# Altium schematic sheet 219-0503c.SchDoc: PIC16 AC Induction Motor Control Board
size C; DrawnBy: Justin Bauer; DocumentNumber: 219-0503; Revision: C; PageSetup: Record=PageOptions¦CenterHorizontal=True¦CenterVertical=True¦PrintScale=0.72¦XCorrection=1.00¦YCorrection=1.00¦PrintKind=2¦BorderSize=5000000¦LeftOffset=0¦BottomOffset=0¦Orientation=2¦PaperLength=1000¦PaperWidth=1000¦Scale=100¦PaperSource=257¦PrintQuality=600¦MediaType=1¦DitherType=10¦PaperKind=11 x 17¦PrintScaleMode=1
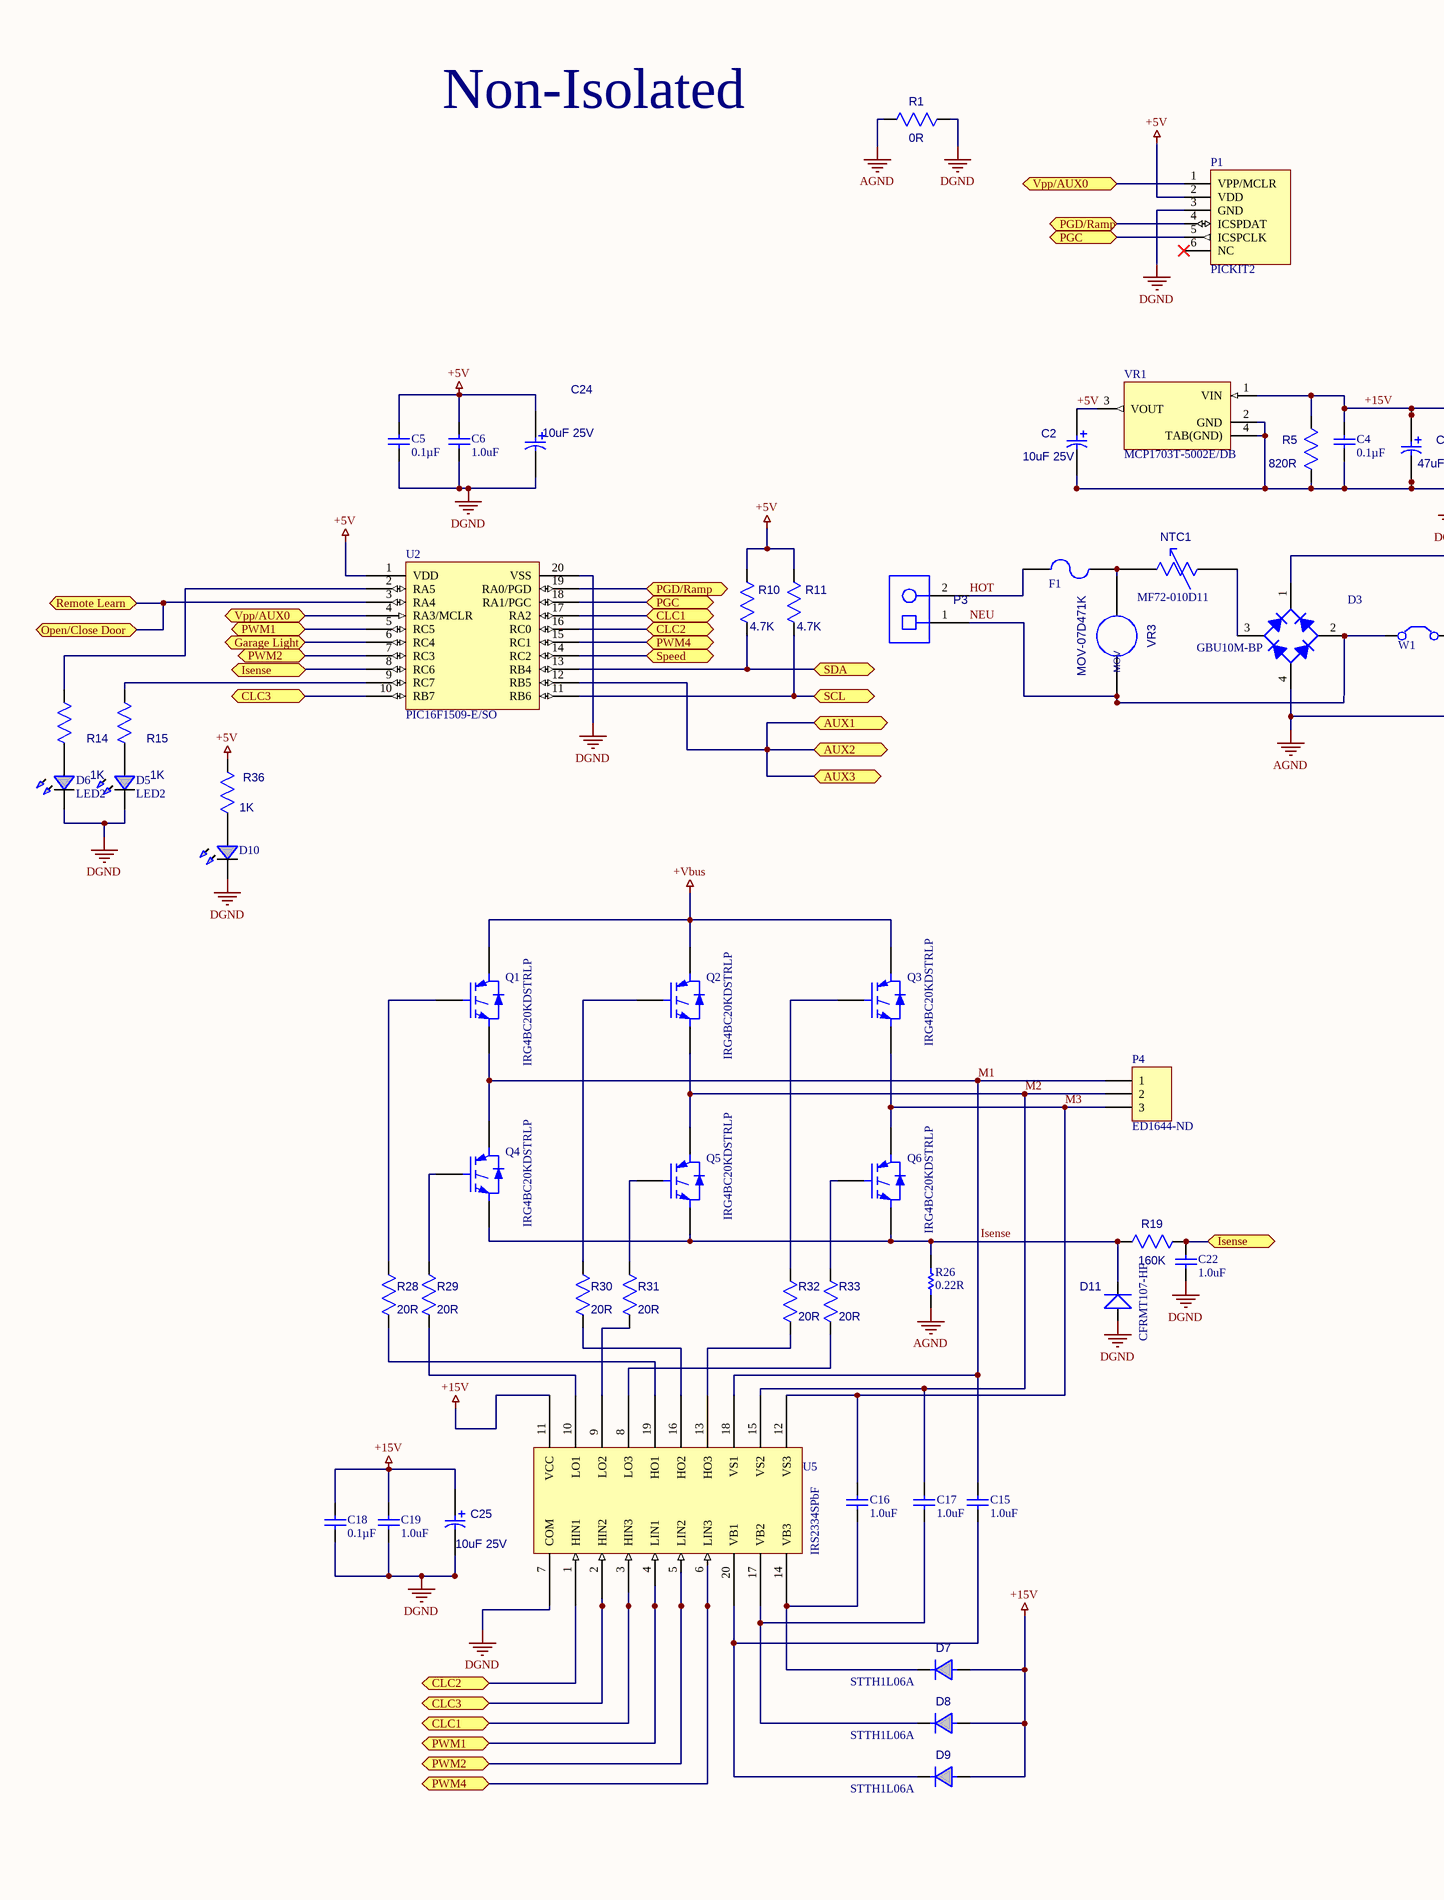
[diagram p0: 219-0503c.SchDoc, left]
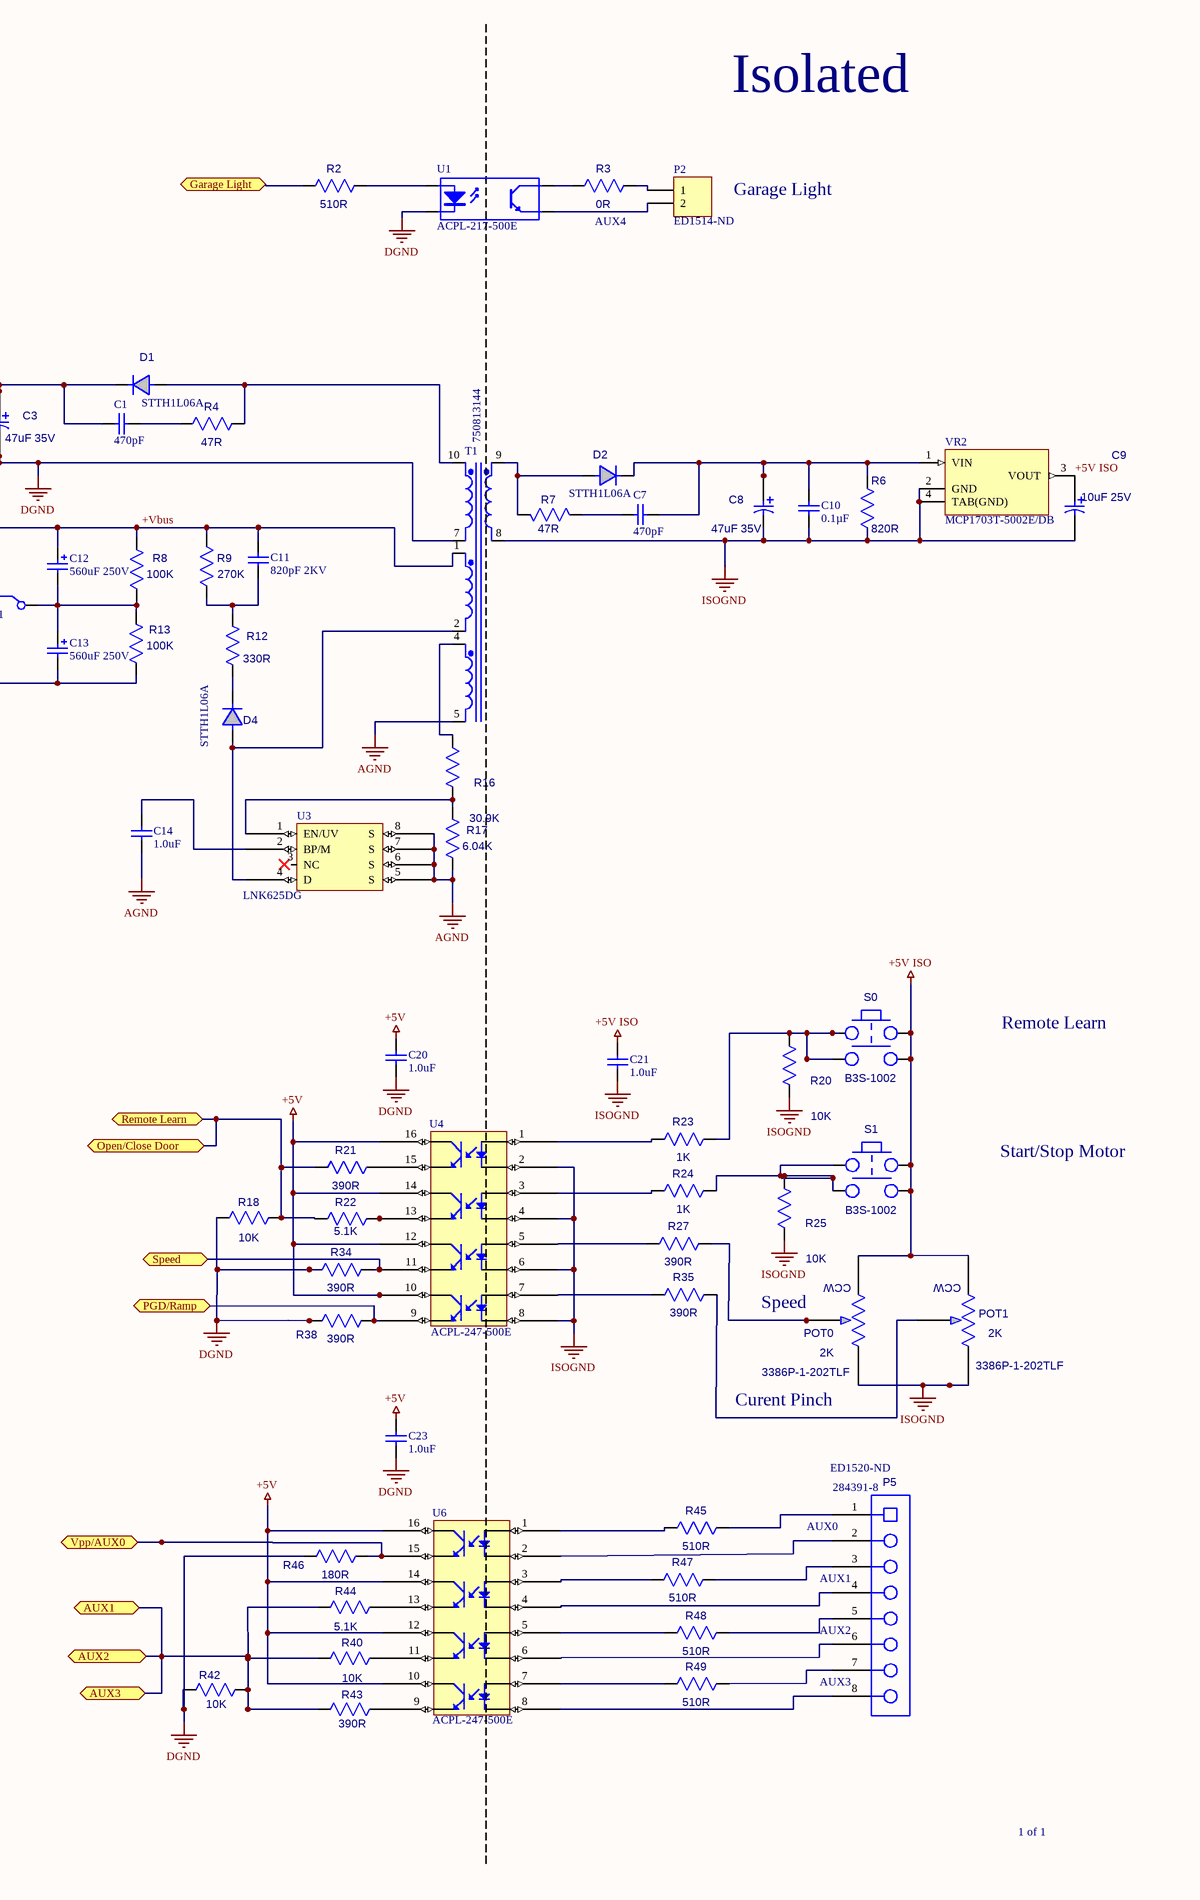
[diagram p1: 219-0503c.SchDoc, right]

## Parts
C1  value 470pF  [CAP_0805]  (hidden comment: CAP0805_470pF)
C2  value 10uF 25V  [CAP079in_5mm]  (hidden comment: UVZ1E100MDD)
C3  value 47uF 35V  [CAP079in_5mm]  (hidden comment: ESH476M035AE3AA)
C4  value 0.1µF  [CAP_0805]  (hidden comment: CAP0805_0.1uF_50V)
C5  value 0.1µF  [CAP_0805]  (hidden comment: CAP0805_0.1uF_50V)
C6  value 1.0uF  [CAP_0805]  (hidden comment: CAP0805_1uF)
C7  value 470pF  [CAP_0805]  (hidden comment: CAP0805_470pF)
C8  value 47uF 35V  [CAP079in_5mm]  (hidden comment: ESH476M035AE3AA)
C9  value 10uF 25V  [CAP079in_5mm]  (hidden comment: UVZ1E100MDD)
C10  value 0.1µF  [CAP_0805]  (hidden comment: CAP0805_0.1uF_50V)
C11  value 820pF 2KV  [CAP_1210]  (hidden comment: CAP1210_820pF)
C12  value 560uF 250V  [CAPPRS10-25x50]  (hidden comment: CAP_560uF_250V)
C13  value 560uF 250V  [CAPPRS10-25x50]  (hidden comment: CAP_560uF_250V)
C14  value 1.0uF  [CAP_0805]  (hidden comment: CAP0805_1uF)
C15  value 1.0uF  [CAP_0805]  (hidden comment: CAP0805_1uF)
C16  value 1.0uF  [CAP_0805]  (hidden comment: CAP0805_1uF)
C17  value 1.0uF  [CAP_0805]  (hidden comment: CAP0805_1uF)
C18  value 0.1µF  [CAP_0805]  (hidden comment: CAP0805_0.1uF_50V)
C19  value 1.0uF  [CAP_0805]  (hidden comment: CAP0805_1uF)
C20  value 1.0uF  [CAP_0805]  (hidden comment: CAP0805_1uF)
C21  value 1.0uF  [CAP_0805]  (hidden comment: CAP0805_1uF)
C22  value 1.0uF  [CAP_0805]  (hidden comment: CAP0805_1uF)
C23  value 1.0uF  [CAP_0805]  (hidden comment: CAP0805_1uF)
C24  value 10uF 25V  [CAP079in_5mm]  (hidden comment: UVZ1E100MDD)
C25  value 10uF 25V  [CAP079in_5mm]  (hidden comment: UVZ1E100MDD)
D1  Part Number: STTH1L06A  [DIODE-SMA]  (hidden comment: DIODE-SMA_STTH1L06A)
D2  Part Number: STTH1L06A  [DIODE-SMA]  (hidden comment: DIODE-SMA_STTH1L06A)
D3  Part Number: GBU10M-BP  [DiodeBridge]  (hidden comment: Bridge1)
D4  Part Number: STTH1L06A  [DIODE-SMA]  (hidden comment: DIODE-SMA_STTH1L06A)
D5  LED2  [LED_0805_RED]
D6  LED2  [LED_0805_GRN]
D7  Part Number: STTH1L06A  [DIODE-SMA]  (hidden comment: DIODE-SMA_STTH1L06A)
D8  Part Number: STTH1L06A  [DIODE-SMA]  (hidden comment: DIODE-SMA_STTH1L06A)
D9  Part Number: STTH1L06A  [DIODE-SMA]  (hidden comment: DIODE-SMA_STTH1L06A)
D10  LED2  [LED_0805_GRN]  (value not drawn)
D11  CFRMT107-HF  [TC3216]
F1  Fuse 2  [FuseSocketHolder]  (value not drawn)
NTC1  MF72-010D11  [THERM_NTC_7.5MM_THERM_NTC_7.5MM(Primary)]
P1  PICKIT2  [TERMSTRIP_TSW-106-07-F-S]
P2  Supplier Part Number 1: ED1514-ND  [TERM BLOCK, 2POS, 3.81.mm]  (hidden comment: ED555/2DS)
P3  OSTTC022162  [2PHDR-200]  (value not drawn)
P4  Supplier Part Number 1: ED1644-ND  [3PHDRX200]  (hidden comment: EDZ350/3)
P5  Part Number1: 284391-8  Supplier Part Number 2: ED1520-ND  [TERM BLOCK, 8POS, 3.5mm]  (hidden comment: Term_BLK_8pos 3.5mm)
POT0  3386P-1-202TLF  value 2K  [POT3386P-1-XXXT]
POT1  3386P-1-202TLF  value 2K  [POT3386P-1-XXXT]
Q1  Part Number: IRG4BC20KDSTRLP  [D2PAK]  (hidden comment: IRG4BC20KD-S_1)
Q2  Part Number: IRG4BC20KDSTRLP  [D2PAK]  (hidden comment: IRG4BC20KD-S_1)
Q3  Part Number: IRG4BC20KDSTRLP  [D2PAK]  (hidden comment: IRG4BC20KD-S_1)
Q4  Part Number: IRG4BC20KDSTRLP  [D2PAK]  (hidden comment: IRG4BC20KD-S_1)
Q5  Part Number: IRG4BC20KDSTRLP  [D2PAK]  (hidden comment: IRG4BC20KD-S_1)
Q6  Part Number: IRG4BC20KDSTRLP  [D2PAK]  (hidden comment: IRG4BC20KD-S_1)
R1  value 0R  [RC_0805]  (hidden comment: RES_RC0805)
R2  value 510R  [RC_0805]  (hidden comment: RES_RC0805)
R3  value 0R  [RC_0805]  (hidden comment: RES_RC0805)
R4  value 47R  [RC_0805]  (hidden comment: RES_RC0805)
R5  value 820R  [RC_0805]  (hidden comment: RES_RC0805)
R6  value 820R  [RC_0805]  (hidden comment: RES_RC0805)
R7  value 47R  [RC_0805]  (hidden comment: RES_RC0805)
R8  value 100K  [RES400_RES400(Primary)]  (hidden comment: CF14JT100K)
R9  value 270K  [RES300_RES300(Primary)]  (hidden comment: RNMF14FTC270K)
R10  value 4.7K  [RC_0805]  (hidden comment: RES_RC0805)
R11  value 4.7K  [RC_0805]  (hidden comment: RES_RC0805)
R12  value 330R  [RES400_RES400(Primary)]  (hidden comment: CF14JT330R)
R13  value 100K  [RES400_RES400(Primary)]  (hidden comment: CF14JT100K)
R14  value 1K  [RC_0805]  (hidden comment: RES_RC0805)
R15  value 1K  [RC_0805]  (hidden comment: RES_RC0805)
R16  value 30.9K  [RC_0805]  (hidden comment: RMCF0805FT30K9)
R17  value 6.04K  [RC_0805]  (hidden comment: RNCP0805FTD6K04)
R18  value 10K  [RC_0805]  (hidden comment: RES_RC0805)
R19  value 160K  [RC_0805]  (hidden comment: RES_RC0805)
R20  value 10K  [RC_0805]  (hidden comment: RES_RC0805)
R21  value 390R  [RC_0805]  (hidden comment: RES_RC0805)
R22  value 5.1K  [RC_0805]  (hidden comment: RES_RC0805)
R23  value 1K  [RC_0805]  (hidden comment: RES_RC0805)
R24  value 1K  [RC_0805]  (hidden comment: RES_RC0805)
R25  value 10K  [RC_0805]  (hidden comment: RES_RC0805)
R26  value 0.22R  [PowerResistor - 5W SQM 5MM Radial]  (hidden comment: 2-1623788-5)
R27  value 390R  [RC_0805]  (hidden comment: RES_RC0805)
R28  value 20R  [RC_0805]  (hidden comment: RES_RC0805)
R29  value 20R  [RC_0805]  (hidden comment: RES_RC0805)
R30  value 20R  [RC_0805]  (hidden comment: RES_RC0805)
R31  value 20R  [RC_0805]  (hidden comment: RES_RC0805)
R32  value 20R  [RC_0805]  (hidden comment: RES_RC0805)
R33  value 20R  [RC_0805]  (hidden comment: RES_RC0805)
R34  value 390R  [RC_0805]  (hidden comment: RES_RC0805)
R35  value 390R  [RC_0805]  (hidden comment: RES_RC0805)
R36  value 1K  [RC_0805]  (hidden comment: RES_RC0805)
R38  value 390R  [RC_0805]  (hidden comment: RES_RC0805)
R40  value 10K  [RC_0805]  (hidden comment: RES_RC0805)
R42  value 10K  [RC_0805]  (hidden comment: RES_RC0805)
R43  value 390R  [RC_0805]  (hidden comment: RES_RC0805)
R44  value 5.1K  [RC_0805]  (hidden comment: RES_RC0805)
R45  value 510R  [RC_0805]  (hidden comment: RES_RC0805)
R46  value 180R  [RC_0805]  (hidden comment: RMCF0805FT180R)
R47  value 510R  [RC_0805]  (hidden comment: RES_RC0805)
R48  value 510R  [RC_0805]  (hidden comment: RES_RC0805)
R49  value 510R  [RC_0805]  (hidden comment: RES_RC0805)
S0  B3S-1002  [SW-B3S1002]
S1  B3S-1002  [SW-B3S1002]
T1  750813144  [Trans_750813134]
U1  ACPL-217-500E  [so4_wstep]
U2  Part Number: PIC16F1509-E/SO  [SO20]  (hidden comment: PIC16F1509-I/SO)
U3  LNK625DG  [so8]
U4  ACPL-247-500E  [SOP127P762-16L]
U5  IRS2334SPbF  [so20]
U6  ACPL-247-500E  [SOP127P762-16L]
VR1  MCP1703T-5002E/DB  [SOT223-3]
VR2  MCP1703T-5002E/DB  [SOT223-3]
VR3  value MOV-07D471K  [MOV_ERZ-V07D431_MOV_ERZ-V07D431(Primary)]  (hidden comment: MOV_MOV-07D471K)
W1  286 SV001  [HEADER_156sp_1X2_DNP]  (value not drawn)  (no BOM)

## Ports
AUX1, AUX2, AUX3, CLC1, CLC2, CLC3, Garage Light, Isense, Open/Close Door, PGC, PGD/Ramp, PWM1, PWM2, PWM4, Remote Learn, SCL, SDA, Speed, Vpp/AUX0

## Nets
+5V: C2.1 C5.2(B) C6.2(B) C20.1(A) C23.1(A) C24.1 P1.2(VDD) R10.2(RO) R11.2(RO) R36.2(RO) U2.1(VDD) U4.10 U4.12 U4.14 U4.16 U6.10 U6.12 U6.14 U6.16 VR1.3(VOUT)
+5V ISO: C9.1 C21.1(A) POT0.1(CCW) POT1.1(CCW) S0.3 S0.4 S1.3 S1.4 VR2.3(VOUT)
+15V: C1.1(A) C3.1 C4.2(B) C18.2(B) C19.2(B) C25.1 D1.1(K) D7.2(A) D8.2(A) D9.2(A) R5.2(RO) U5.11(VCC) VR1.1(VIN)
+Vbus: C11.2(B) C12.1 D3.1(K) Q1.2(C) Q2.2(C) Q3.2(C) R8.B R9.B T1.1(Pri-)
AGND: C13.2 C14.1(A) D3.4(A) R1.1(RI) R13.A R17.1(RI) R26.1 T1.5(Sec3-) U3.5(S) U3.6(S) U3.7(S) U3.8(S)
DGND: C2.2 C3.2 C4.1(A) C5.1(A) C6.1(A) C18.1(A) C19.1(A) C20.2(B) C22.1(A) C23.2(B) C24.2 C25.2 D5.1(K) D6.1(K) D10.1(K) D11.1(A) P1.3(GND) R1.2(RO) R5.1(RI) R18.2(RO) R34.1(RI) R38.1(RI) R42.2(RO) R46.1(RI) T1.7(Sec1-) U1.2(K) U2.20(VSS) U5.7(COM) VR1.2(GND) VR1.4(TAB(GND))
ISOGND: C8.2 C9.2 C10.2(B) C21.2(B) POT0.3(CW) POT1.3(CW) R6.1(RI) R20.1(RI) R25.1(RI) T1.8(Sec-) U4.2 U4.4 U4.6 U4.8 VR2.2(GND) VR2.4(TAB(GND))
AUX1: R40.2(RO) R42.1(RI) R43.2(RO) R44.2(RO) U2.12(RB5) ; port AUX1, port AUX2, port AUX3
CLC1: U2.17(RA2) U5.3(HIN3) ; port CLC1
CLC2: U2.16(RC0) U5.1(HIN1) ; port CLC2
CLC3: U2.10(RB7) U5.2(HIN2) ; port CLC3
Garage Light: R2.1(RI) U2.6(RC4) ; port Garage Light
HOT: F1.1 P3.2(P2)
Isense: D11.2(K) Q4.3(E) Q5.3(E) Q6.3(E) R19.1(RI) R26.2
Isense: C22.2(B) R19.2(RO) U2.8(RC6) ; port Isense  [a separate net that carries the same name]
M1: C15.2(B) P4.1 Q1.3(E) Q4.2(C) U5.18(VS1)
M2: C17.1(A) P4.2 Q2.3(E) Q5.2(C) U5.15(VS2)
M3: C16.2(B) P4.3 Q3.3(E) Q6.2(C) U5.12(VS3)
NEU: D3.2(C) P3.1(P1) VR3.B W1.1(C1)
Open/Close Door: R18.1(RI) R21.2(RO) R22.2(RO) U2.3(RA4) ; port Remote Learn, port Open/Close Door
PGC: P1.5(ICSPCLK) U2.18(RA1/PGC) ; port PGC
PGD/Ramp: P1.4(ICSPDAT) R38.2(RO) U2.19(RA0/PGD) U4.9 ; port PGD/Ramp
PWM1: U2.5(RC5) U5.4(LIN1) ; port PWM1
PWM2: U2.7(RC3) U5.5(LIN2) ; port PWM2
PWM4: U2.15(RC1) U5.6(LIN3) ; port PWM4
SCL: R11.1(RI) U2.11(RB6) ; port SCL
SDA: R10.1(RI) U2.13(RB4) ; port SDA
Speed: R34.2(RO) U2.14(RC2) U4.11 ; port Speed
Vpp/AUX0: P1.1(VPP/MCLR) R46.2(RO) U2.4(RA3/MCLR) U6.15 ; port Vpp/AUX0
NetC1_2: C1.2(B) R4.1(RI)
NetC7_1: C7.1(A) R7.1(RI)
NetC7_2: C7.2(B) C8.1 C10.1(A) D2.1(K) R6.2(RO) VR2.1(VIN)
NetC11_1: C11.1(A) R9.A R12.B
NetC12_2: C12.2 C13.1 R8.A R13.B W1.2(C2)
NetC14_2: C14.2(B) U3.2(BP/M)
NetC15_1: C15.1(A) D9.1(K) U5.20(VB1)
NetC16_1: C16.1(A) D7.1(K) U5.14(VB3)
NetC17_2: C17.2(B) D8.1(K) U5.17(VB2)
NetD1_2: D1.2(A) R4.2(RO) T1.10(Sec1+)
NetD2_2: D2.2(A) R7.2(RO) T1.9(Sec+)
NetD3_3: D3.3(C) NTC1.1
NetD4_1: D4.1(K) R12.A
NetD4_2: D4.2(A) T1.2(PRI+) U3.4(D)
NetD5_2: D5.2(A) R15.1(RI)
NetD6_2: D6.2(A) R14.1(RI)
NetD10_2: D10.2(A) R36.1(RI)
NetF1_2: F1.2 NTC1.2 VR3.A
NetP2_1: P2.1 R3.2(RO)
NetP2_2: P2.2 U1.3(E)
NetP5_1: P5.1(P1) R45.2(RO)
NetP5_2: P5.2(P2) U6.2
NetP5_3: P5.3(P3) R47.2(RO)
NetP5_4: P5.4(P4) U6.4
NetP5_5: P5.5(P5) R48.2(RO)
NetP5_6: P5.6(P6) U6.6
NetP5_7: P5.7(P7) R49.2(RO)
NetP5_8: P5.8(P8) U6.8
NetPOT0_2: POT0.2(WIPER) R27.2(RO)
NetPOT1_2: POT1.2(WIPER) R35.2(RO)
NetQ1_1: Q1.1(G) R28.2(RO)
NetQ2_1: Q2.1(G) R30.2(RO)
NetQ3_1: Q3.1(G) R32.2(RO)
NetQ4_1: Q4.1(G) R29.2(RO)
NetQ5_1: Q5.1(G) R31.2(RO)
NetQ6_1: Q6.1(G) R33.2(RO)
NetR2_2: R2.2(RO) U1.1(A)
NetR3_1: R3.1(RI) U1.4(C)
NetR14_2: R14.2(RO) U2.2(RA5)
NetR15_2: R15.2(RO) U2.9(RC7)
NetR16_1: R16.1(RI) R17.2(RO) U3.1(EN/UV)
NetR16_2: R16.2(RO) T1.4(Sec3+)
NetR20_2: R20.2(RO) R23.2(RO) S0.1 S0.2
NetR21_1: R21.1(RI) U4.15
NetR22_1: R22.1(RI) U4.13
NetR23_1: R23.1(RI) U4.1
NetR24_1: R24.1(RI) U4.3
NetR24_2: R24.2(RO) R25.2(RO) S1.1 S1.2
NetR27_1: R27.1(RI) U4.5
NetR28_1: R28.1(RI) U5.19(HO1)
NetR29_1: R29.1(RI) U5.10(LO1)
NetR30_1: R30.1(RI) U5.16(HO2)
NetR31_1: R31.1(RI) U5.9(LO2)
NetR32_1: R32.1(RI) U5.13(HO3)
NetR33_1: R33.1(RI) U5.8(LO3)
NetR35_1: R35.1(RI) U4.7
NetR40_1: R40.1(RI) U6.11
NetR43_1: R43.1(RI) U6.9
NetR44_1: R44.1(RI) U6.13
NetR45_1: R45.1(RI) U6.1
NetR47_1: R47.1(RI) U6.3
NetR48_1: R48.1(RI) U6.5
NetR49_1: R49.1(RI) U6.7

Not connected (* = marked no-connect by the designer): P1 6(NC)*; U3 3(NC)

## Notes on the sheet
- Isolated
- Non-Isolated
- (near R3) AUX4
- Garage Light
- Remote Learn
- Start/Stop Motor
- Speed
- (near POT0) Curent Pinch
- (near P5) AUX0
- (near P5) AUX1
- (near P5) AUX2
- (near P5) AUX3
- 1 of 1

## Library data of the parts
C1 C7 = CAP0805_470pF: CAP CER 470PF 100V 5% NP0 0805; Part Number: CL21C471JCCNNNC; Dielectric Characteristic: C0G; Voltage Rating: 100; Capacitor Case Style: 0805; No. of Pins: 2
C2 C9 C24 C25 = CAP100RP_10uF_25V: CAP ALUM 10UF 25V 20% RADIAL
C3 C8 = CAP100RP_47uF_35V: CAP ALUM 47UF 35V 20% RADIAL
C4 C5 C10 = CAP0805_0.1uF_50V: Cap, Ceramic, 0.1uF, 50V X7R; Part Number: 08055C104MAT2A; Manufacturer 1: AVX Corporation; Tolerance: ±20%
C6 C14-C17 C19-C23 = CAP0805_1uF: CAP CER 1UF 50V 10% X5R 080; Part Number: UMK212BJ105KG-T; Dielectric Characteristic: X7; Voltage Rating: 50; Capacitor Case Style: 0805; No. of Pins: 2
C11 = CAP1210_820pF: CAP CER 820PF 2KV 10% X7R 1210; Manufacturer: TDK; Part Number: 1210GC821KAT1A; Dielectric Characteristic: X5; Capacitance Tolerance: ± 20%; Voltage Rating: 2000; Temperature Coefficient: ± 15%; Capacitor Case Style: 0805; No. of Pins: 2; Tolerance: ±20%
C12 C13 = CAP_560uF_250V: CAP ALUM 560UF 250V 20% SNAP; Part Number: EET-UQ2E561CA
C18 = CAP0805_0.1uF_50V: Cap, Ceramic, 0.1uF, 50V X7R; Manufacturer 1: AVX Corporation; Manufacturer Part Number 1: 08055C104MAT2A; Tolerance: ±20%
D1 D2 D4 D7-D9 = DIODE-SMA_STTH1L06A: DIODE ULTRA FAST 600V 1A SMA; Manufacturer: ST Microelectronics; Value: {Value}
D3 = Bridge1: Full Wave Diode Bridge
D5 = LED_0805_YEL: LED, SMD, YEL, 0805 package; Manufacturer: Kingbright Corp; Part Number: APT2012YC; Color: Yellow; Current - Test: 20mA; Wavelength - Dominant: 588nm; Wavelength - Peak: 590nm; Millicandela Rating: 150mcd; Voltage - Forward (Vf) Typ: 2V; Lens Type: Clear; Lens Style/Size: Rectangle, 1.3mm x 1.25mm; Viewing Angle: 120°
D6 D10 = LED_0805_GRN: LED, SMD, GRN, 0805 package; Manufacturer: Kingbright Corp; Part Number: APT2012CGCK; Color: Green; Current - Test: 20mA; Wavelength - Dominant: 570nm; Wavelength - Peak: 574nm; Millicandela Rating: 50mcd; Voltage - Forward (Vf) Typ: 2.1V; Lens Type: Clear; Lens Style/Size: Rectangle, 1.3mm x 1.25mm; Viewing Angle: 120°
D11 = DIODE_FAST_SOD123
F1 = Fuse 2: FUSEHOLDER 22.5MM PCB 5X20MM BK; Part Number: 0031.8201
NTC1 = THERM_NTC_MF72-010D11: Current Limiter Inrush 100R 20%
P1 = HEADER_1X6_PICKIT2: Header, Pickit2, 1X6 0.1sp; Manufacturer: SAMTEC; Part Number: TSW-106-07-F-S
P2 = HDR_TERM_BLK3.5mm2POS: TERMINAL BLOCK 3.5MM 2POS PCB
P3 = 2PHDR-200: Value: {Value}
P4 = HDR_TERM_BLK5.08mm3POS: TERMINAL BLOCK 5.08MM 3POS PCB
P5 = Term_BLK_8pos 3.5mm: Part Number: ED555/8DS
POT0 POT1 = POT-3386P-1-202TLF
Q1-Q6 = IRG4BC20KD-S_1: Insulated Gate Bipolar Transistor with Ultrafast Soft Recovery Diode; Note: Terminal 2 (collector) is the BASE
R1 = RES_RC0805_0R: RES 0.0 OHM 1/8W 0805 SMD; Part Number: RMCF0805ZT0R00; Manufacturer: Stackpole Electronics; Suplier1: Digikey
R2 = RES_RC0805_510R: RES 510 OHM 1/8W 0805 SMD; Part Number: RMCF0805FT510R; Manufacturer: Stackpole Electronics
R3 = RES_RC0805_0R: RES 0.0 OHM 1/8W 0805 SMD; Manufacturer: Stackpole Electronics; Part Number: RMCF0805ZT0R00; Suplier1: Digikey
R4 R7 = RES_RC0805_47R: RES 47 OHM 1/8W 0805 SMD; Manufacturer Part Number: RMCF0805FT47R0; Manufacturer: Stackpole Electronics; Suplier1: Digikey
R5 R6 = RES_RC0805_820R: RES 820 OHM 1/8W 0805 SMD; Manufacturer Part Number: RMCF0805FT820R; Manufacturer: Stackpole Electronics
R8 R13 = RES400_100K: RES 100K OHM 1/4W 5% CARBON FILM
R9 = RES300_270K: RES 270K OHM 1/4W 5% CARBON FILM
R10 R11 = RES_RC0805_4.7K: RES 4.7K OHM 1/8W 1% 0805 SMD; Manufacturer: Stackpole Electronics; Manufacturer Part Number: RMCF0805FT4K70
R12 = RES400_330R: RES 330 OHM 1/4W 5% CARBON FILM
R14 R15 R23 R24 R36 = RES_RC0805_1K: RES 1K OHM 1/8W 1% 0805 SMD; Manufacturer Part Number: RMCF0805FT1K00; Manufacturer: Stackpole Electronics; Suplier1: Digikey
R16 = RES_RC0805_30.9K: RES 30.9K OHM 1/8W 1% 0805 SMD; Manufacturer: Stackpole Electronics
R17 = RES_RC0805_6.04K: RES 6.04K OHM 1/8W 1% 0805 SMD; Manufacturer: Stackpole Electronics
R18 R20 R25 R40 R42 = RES_RC0805_10K: RES 10K OHM 1/8W 1% 0805 SMD; Manufacturer Part Number: RMCF0805FT10K0; Manufacturer: Stackpole Electronics
R19 = RES_RC0805_160K: RES 160K OHM 1/8W 1% 0805 SMD; Manufacturer Part Number: RMCF0805FT160K; Manufacturer: Stackpole Electronics; Suplier1: Digikey
R21 R27 R34 R35 R38 R43 = RES_RC0805_390R: RES 390 OHM 1/8W 0805 SMD; Manufacturer Part Number: RMCF0805FT390R; Manufacturer: Stackpole Electronics
R22 R44 = RES_RC0805_5.1K: RES 5.1K OHM 1/8W 1% 0805 SMD; Manufacturer Part Number: RMCF0805FT5K10; Manufacturer: Stackpole Electronics
R26 = Res_5W_0R22vertical: RES 0.22 OHM 5W 5% RADIAL; Manufacture: TE Connectivity
R28-R33 = RES_RC0805_20R: RES 20 OHM 1/8W 1% 0805 SMD; Manufacturer Part Number: RMCF0805FT20R0; Manufacturer: Stackpole Electronics
R45 R47-R49 = RES_RC0805_510R: RES 510 OHM 1/8W 0805 SMD; Manufacturer Part Number: RMCF0805FT510R; Manufacturer: Stackpole Electronics
R46 = RES_RC0805_180R: RES 180 OHM 1/8W 1% 0805 SMD; Manufacturer: Stackpole Electronics; Suplier1: Digikey
S0 S1 = SW-B3S1002: SWITCH TACTILE SPST-NO 0.05A 24V
T1 = Trans_750813144: Four-winding Transformer (Non-Ideal); Sim Note: Enter the turns ratios, Core loss resistance, Magnetising Reactance, Leakage Reactances and Resistances referred to the primary side into the parameter fields.
U1 = Opto_ACPL-217-500E: 4-Pin Phototransistor Optocoupler
U2 = PIC16F1509-I/SO: 8-bit Micro
U3 = LNK625DG: AC/DC converter
U4 U6 = Optoisolator_ACPL-247-500E: ISOLATOR 3KVRMS 4CH TRANS 16SOI
U5 = IRS2334SPbF: IC MOSFET DRIVER
VR1 VR2 = MCP1703T-5002E/DB: High Voltage Regulator, 5V, 70mA, SOT-223; Input Voltage MAX: 30 V; Number of Outputs: 1; Output Type: Fixed; Dropout Voltage (Max): 1.3 V at 70 mA; Voltage Regulation Accuracy: 2.5 %; Line Regulation: +/- 0.0002 % / V; Load Regulation: +/- 0.2 %; Polarity: Positive
VR3 = MOV_ERZ-V07D431: Resistor
W1 = Jumper_156"sp_DNP: Jumper Wire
